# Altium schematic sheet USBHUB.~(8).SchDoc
size A
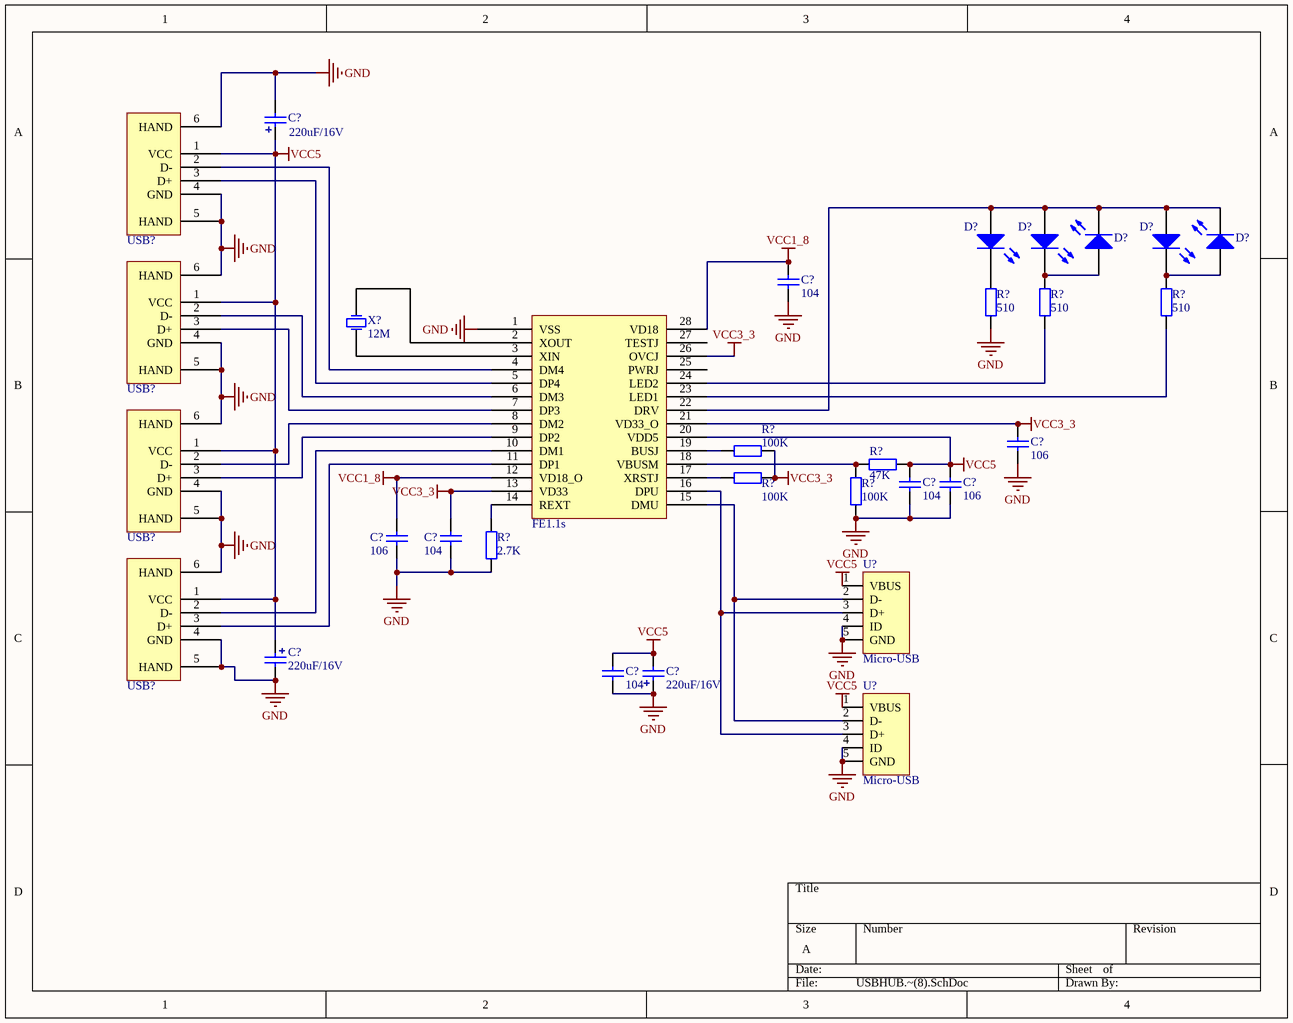
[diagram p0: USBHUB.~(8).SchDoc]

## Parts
(Parts that share a designator on the sheet are numbered #1, #2 ... from top to bottom, then left to right.)
C?#1  value 220uF/16V  [Cap_47uF/16V]  (hidden comment: Cap_Pol)
C?#2  value 104  [2012[0805]-C]  (hidden comment: Cap1)
C?#3  value 106  [2012[0805]-C]  (hidden comment: Cap1)
C?#4  value 104  [2012[0805]-C]  (hidden comment: Cap1)
C?#5  value 106  [2012[0805]-C]  (hidden comment: Cap1)
C?#6  value 106  [2012[0805]-C]  (hidden comment: Cap1)
C?#7  value 104  [2012[0805]-C]  (hidden comment: Cap1)
C?#8  value 220uF/16V  [Cap_47uF/16V]  (hidden comment: Cap_Pol)
C?#9  value 104  [2012[0805]-C]  (hidden comment: Cap1)
C?#10  value 220uF/16V  [Cap_47uF/16V]  (hidden comment: Cap_Pol)
D?#1  LED  [LED1]  (value not drawn)
D?#2  LED  [LED1]  (value not drawn)
D?#3  LED  [LED1]  (value not drawn)
D?#4  LED  [LED1]  (value not drawn)
D?#5  LED  [LED1]  (value not drawn)
FE1.1s  FE1.1s  [SSOP-28]  (value not drawn)
R?#1  value 510  [2012[0805]-R]  (hidden comment: Res1)
R?#2  value 510  [2012[0805]-R]  (hidden comment: Res1)
R?#3  value 510  [2012[0805]-R]  (hidden comment: Res1)
R?#4  value 100K  [2012[0805]-R]  (hidden comment: Res1)
R?#5  value 47K  [2012[0805]-R]  (hidden comment: Res1)
R?#6  value 100K  [2012[0805]-R]  (hidden comment: Res1)
R?#7  value 100K  [2012[0805]-R]  (hidden comment: Res1)
R?#8  value 2.7K  [2012[0805]-R]  (hidden comment: Res1)
U?#1  Micro-USB  [Micro-USB]
U?#2  Micro-USB  [Micro-USB]
USB?#1  USB  [USB2.5-2V4A]  (value not drawn)
USB?#2  USB  [USB2.5-2V4A]  (value not drawn)
USB?#3  USB  [USB2.5-2V4A]  (value not drawn)
USB?#4  USB  [USB2.5-2V4A]  (value not drawn)
X?  12M  [XTAL]

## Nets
GND: C?#1.2 C?#2.2 C?#3.1 C?#4.1 C?#5.1 C?#6.1 C?#7.1 C?#8.2 C?#9.1 C?#10.1 R?#1.1 R?#7.1 R?#8.1 U?#1.4(ID) U?#1.5(GND) U?#2.4(ID) U?#2.5(GND) USB?#1.4(GND) USB?#1.5(HAND) USB?#1.6(HAND) USB?#2.4(GND) USB?#2.5(HAND) USB?#2.6(HAND) USB?#3.4(GND) USB?#3.5(HAND) USB?#3.6(HAND) USB?#4.4(GND) USB?#4.5(HAND) USB?#4.6(HAND)
VCC1_8: C?#2.1 C?#6.2 FE1.1s.12(VD18_O) FE1.1s.28(VD18)
VCC3_3: C?#3.2 C?#7.2 FE1.1s.13(VD33) FE1.1s.21(VD33_O) FE1.1s.26(OVCJ) R?#4.2 R?#6.2
VCC5: C?#1.1 C?#4.2 C?#5.2 C?#8.1 C?#9.2 C?#10.2 FE1.1s.20(VDD5) R?#5.2 U?#1.1(VBUS) U?#2.1(VBUS) USB?#1.1(VCC) USB?#2.1(VCC) USB?#3.1(VCC) USB?#4.1(VCC)
NetD?#1_1: D?#1.1(A) D?#2.1(A) D?#3.1(A) D?#4.2(K) D?#5.2(K) FE1.1s.22(DRV)
NetD?#1_2: D?#1.2(K) R?#1.2
NetD?#2_2: D?#2.2(K) D?#4.1(A) R?#2.2
NetD?#3_2: D?#3.2(K) D?#5.1(A) R?#3.2
NetFE1.1s_4: FE1.1s.4(DM4) USB?#1.2(D-)
NetFE1.1s_5: FE1.1s.5(DP4) USB?#1.3(D+)
NetFE1.1s_6: FE1.1s.6(DM3) USB?#2.2(D-)
NetFE1.1s_7: FE1.1s.7(DP3) USB?#2.3(D+)
NetFE1.1s_8: FE1.1s.8(DM2) USB?#3.2(D-)
NetFE1.1s_9: FE1.1s.9(DP2) USB?#3.3(D+)
NetFE1.1s_10: FE1.1s.10(DM1) USB?#4.2(D-)
NetFE1.1s_11: FE1.1s.11(DP1) USB?#4.3(D+)
NetFE1.1s_14: FE1.1s.14(REXT) R?#8.2
NetFE1.1s_15: FE1.1s.15(DMU) U?#1.2(D-) U?#2.2(D-)
NetFE1.1s_16: FE1.1s.16(DPU) U?#1.3(D+) U?#2.3(D+)
NetFE1.1s_17: FE1.1s.17(XRSTJ) R?#6.1
NetFE1.1s_18: FE1.1s.18(VBUSM) R?#5.1 R?#7.2
NetFE1.1s_19: FE1.1s.19(BUSJ) R?#4.1
NetFE1.1s_23: FE1.1s.23(LED1) R?#3.1
NetFE1.1s_24: FE1.1s.24(LED2) R?#2.1

Not connected (* = marked no-connect by the designer): FE1.1s 1(VSS) 2(XOUT) 3(XIN) 25(PWRJ) 27(TESTJ); X? 1(OSC1) 2(OSC2)

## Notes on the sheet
- Labels drawn without touching a wire or pin: GND

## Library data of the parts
C?#1 C?#8 C?#10 = Cap_Pol: Capacitor
C?#2-C?#7 C?#9 = Cap1: Capacitor
D?#1-D?#5 = LED1: Typical INFRARED GaAs LED
R?#1-R?#8 = Res1: Resistor
X? = XTAL_1: Crystal Oscillator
